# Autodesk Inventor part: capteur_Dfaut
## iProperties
Created: 2007-07
Part Number: capteur_Dfaut
Document SubType Name: Modeling
Designer: EF
Density: 1 g/cm^3
Mass: 4.39659 g
Surface Area: 21.4513 cm^2
Volume: 4.39659 cm^3
Author: EF
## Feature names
1. Extrusion2
2. Extrusion1
3. Hole2
4. Hole1
5. Fillet4
6. Fillet3
7. Fillet2
8. Fillet1
